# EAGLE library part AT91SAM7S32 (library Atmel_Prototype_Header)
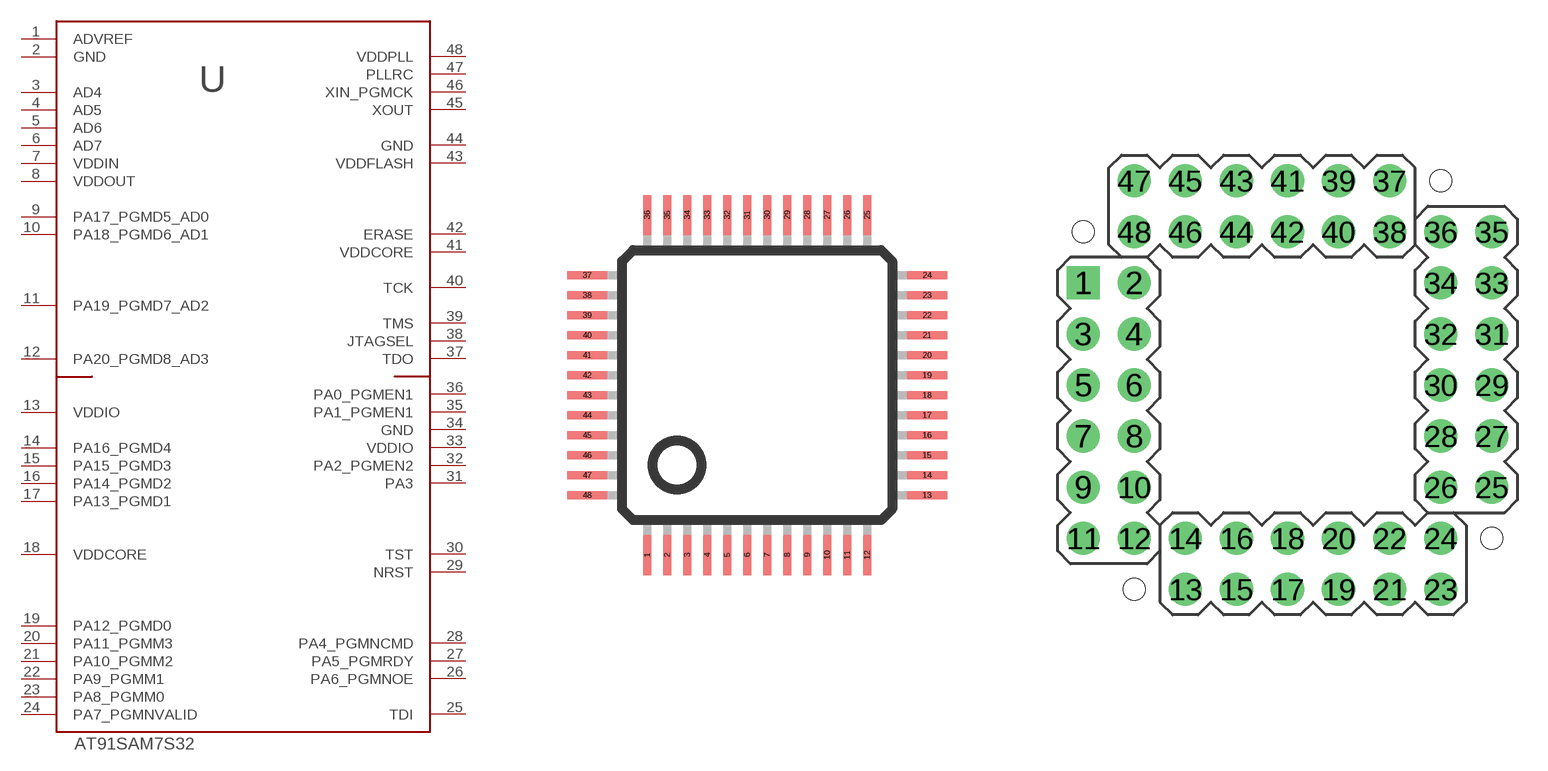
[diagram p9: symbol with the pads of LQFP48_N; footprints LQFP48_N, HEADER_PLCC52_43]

Designator prefix U

## AT91SAM7S32_LQFP48_N  [LQFP48_N]
1  ADVREF  in
2  GND
3  AD4
4  AD5
5  AD6
6  AD7
7  VDDIN
8  VDDOUT
9  PA17_PGMD5_AD0
10  PA18_PGMD6_AD1
11  PA19_PGMD7_AD2
12  PA20_PGMD8_AD3
13  VDDIO
14  PA16_PGMD4
15  PA15_PGMD3  in
16  PA14_PGMD2  pwr
17  PA13_PGMD1  pwr
18  VDDCORE
19  PA12_PGMD0
20  PA11_PGMM3
21  PA10_PGMM2
22  PA9_PGMM1
23  PA8_PGMM0
24  PA7_PGMNVALID
25  TDI
26  PA6_PGMNOE
27  PA5_PGMRDY  out
28  PA4_PGMNCMD  out
29  NRST  out
30  TST  out
31  PA3
32  PA2_PGMEN2
33  VDDIO
34  GND
35  PA1_PGMEN1
36  PA0_PGMEN1
37  TDO
38  JTAGSEL
39  TMS
40  TCK  pwr
41  VDDCORE  in
42  ERASE  in
43  VDDFLASH  in
44  GND  in
45  XOUT  in
46  XIN_PGMCK
47  PLLRC
48  VDDPLL

## AT91SAM7S32_PLCC52_43  [HEADER_PLCC52_43]
Pads as for LQFP48_N

## AT91SAM7S32_PLCC52_35  [HEADER_PLCC52_35]
Pads as for LQFP48_N

## AT91SAM7S32_LQFP48_W  [LQFP48_W]
Pads as for LQFP48_N

## Footprint LQFP48_N (pad centres in mm)
48-pin plastic LQFP (FPT-48P-M26) www.fma.fujitsu.com/pdf/e713717.pdf
smd 0.2 x 1: 1 -2.75,-4.25; 2 -2.25,-4.25; 3 -1.75,-4.25; 4 -1.25,-4.25; 5 -0.75,-4.25; 6 -0.25,-4.25; 7 0.25,-4.25; 8 0.75,-4.25; 9 1.25,-4.25; 10 1.75,-4.25; 11 2.25,-4.25; 12 2.75,-4.25; 25 2.75,4.25; 26 2.25,4.25; 27 1.75,4.25; 28 1.25,4.25; 29 0.75,4.25; 30 0.25,4.25; 31 -0.25,4.25; 32 -0.75,4.25; 33 -1.25,4.25; 34 -1.75,4.25; 35 -2.25,4.25; 36 -2.75,4.25
smd 1 x 0.2: 13 4.25,-2.75; 14 4.25,-2.25; 15 4.25,-1.75; 16 4.25,-1.25; 17 4.25,-0.75; 18 4.25,-0.25; 19 4.25,0.25; 20 4.25,0.75; 21 4.25,1.25; 22 4.25,1.75; 23 4.25,2.25; 24 4.25,2.75; 37 -4.25,2.75; 38 -4.25,2.25; 39 -4.25,1.75; 40 -4.25,1.25; 41 -4.25,0.75; 42 -4.25,0.25; 43 -4.25,-0.25; 44 -4.25,-0.75; 45 -4.25,-1.25; 46 -4.25,-1.75; 47 -4.25,-2.25; 48 -4.25,-2.75

## Footprint HEADER_PLCC52_43 (pad centres in mm)
drill 1.1 square: 1 -10.16,5.08
drill 1.1 round: 2 -7.62,5.08; 3 -10.16,2.54; 4 -7.62,2.54; 5 -10.16,0; 6 -7.62,0; 7 -10.16,-2.54; 8 -7.62,-2.54; 9 -10.16,-5.08; 10 -7.62,-5.08; 11 -10.16,-7.62; 12 -7.62,-7.62; 13 -5.08,-10.16; 14 -5.08,-7.62; 15 -2.54,-10.16; 16 -2.54,-7.62; 17 0,-10.16; 18 0,-7.62; 19 2.54,-10.16; 20 2.54,-7.62; 21 5.08,-10.16; 22 5.08,-7.62; 23 7.62,-10.16; 24 7.62,-7.62; 25 10.16,-5.08; 26 7.62,-5.08; 27 10.16,-2.54; 28 7.62,-2.54; 29 10.16,0; 30 7.62,0; 31 10.16,2.54; 32 7.62,2.54; 33 10.16,5.08; 34 7.62,5.08; 35 10.16,7.62; 36 7.62,7.62; 37 5.08,10.16; 38 5.08,7.62; 39 2.54,10.16; 40 2.54,7.62; 41 0,10.16; 42 0,7.62; 43 -2.54,10.16; 44 -2.54,7.62; 45 -5.08,10.16; 46 -5.08,7.62; 47 -7.62,10.16; 48 -7.62,7.62
hole 1.1 at -10.16,7.62
hole 1.1 at -7.62,-10.16
hole 1.1 at 10.16,-7.62
hole 1.1 at 7.62,10.16

## Footprint HEADER_PLCC52_35 (pad centres in mm)
drill 0.9 square: 1 -10.16,5.08
drill 0.9 round: 2 -7.62,5.08; 3 -10.16,2.54; 4 -7.62,2.54; 5 -10.16,0; 6 -7.62,0; 7 -10.16,-2.54; 8 -7.62,-2.54; 9 -10.16,-5.08; 10 -7.62,-5.08; 11 -10.16,-7.62; 12 -7.62,-7.62; 13 -5.08,-10.16; 14 -5.08,-7.62; 15 -2.54,-10.16; 16 -2.54,-7.62; 17 0,-10.16; 18 0,-7.62; 19 2.54,-10.16; 20 2.54,-7.62; 21 5.08,-10.16; 22 5.08,-7.62; 23 7.62,-10.16; 24 7.62,-7.62; 25 10.16,-5.08; 26 7.62,-5.08; 27 10.16,-2.54; 28 7.62,-2.54; 29 10.16,0; 30 7.62,0; 31 10.16,2.54; 32 7.62,2.54; 33 10.16,5.08; 34 7.62,5.08; 35 10.16,7.62; 36 7.62,7.62; 37 5.08,10.16; 38 5.08,7.62; 39 2.54,10.16; 40 2.54,7.62; 41 0,10.16; 42 0,7.62; 43 -2.54,10.16; 44 -2.54,7.62; 45 -5.08,10.16; 46 -5.08,7.62; 47 -7.62,10.16; 48 -7.62,7.62
hole 0.9 at -10.16,7.62
hole 0.9 at -7.62,-10.16
hole 0.9 at 10.16,-7.62
hole 0.9 at 7.62,10.16

## Footprint LQFP48_W (pad centres in mm)
smd 0.27 x 1: 1 -2.75,-4.25; 2 -2.25,-4.25; 3 -1.75,-4.25; 4 -1.25,-4.25; 5 -0.75,-4.25; 6 -0.25,-4.25; 7 0.25,-4.25; 8 0.75,-4.25; 9 1.25,-4.25; 10 1.75,-4.25; 11 2.25,-4.25; 12 2.75,-4.25; 25 2.75,4.25; 26 2.25,4.25; 27 1.75,4.25; 28 1.25,4.25; 29 0.75,4.25; 30 0.25,4.25; 31 -0.25,4.25; 32 -0.75,4.25; 33 -1.25,4.25; 34 -1.75,4.25; 35 -2.25,4.25; 36 -2.75,4.25
smd 1 x 0.27: 13 4.25,-2.75; 14 4.25,-2.25; 15 4.25,-1.75; 16 4.25,-1.25; 17 4.25,-0.75; 18 4.25,-0.25; 19 4.25,0.25; 20 4.25,0.75; 21 4.25,1.25; 22 4.25,1.75; 23 4.25,2.25; 24 4.25,2.75; 37 -4.25,2.75; 38 -4.25,2.25; 39 -4.25,1.75; 40 -4.25,1.25; 41 -4.25,0.75; 42 -4.25,0.25; 43 -4.25,-0.25; 44 -4.25,-0.75; 45 -4.25,-1.25; 46 -4.25,-1.75; 47 -4.25,-2.25; 48 -4.25,-2.75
